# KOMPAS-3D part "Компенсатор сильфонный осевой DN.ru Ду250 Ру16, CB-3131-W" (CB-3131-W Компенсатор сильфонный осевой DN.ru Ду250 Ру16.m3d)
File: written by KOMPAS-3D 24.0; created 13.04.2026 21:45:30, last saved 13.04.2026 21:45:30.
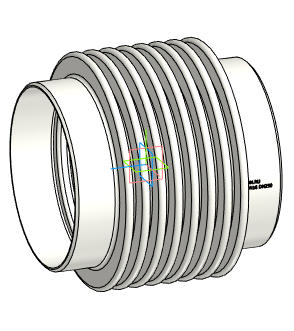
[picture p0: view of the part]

Document properties: Автор: DN.RU; Полное имя файла: D:\PROJECT CAD\DN.RU\...197(ACTUALE). CB-3131-W Компенсатор сильфонный осевой DN.ru\Исходники\DN250\CB-3131-W Компенсатор сильфонный осевой DN.ru Ду250 Ру16.m3d

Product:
- Body: Твердое тело1  | qty 1
    Масса: 21.471183
- Part/product: Компенсатор сильфонный осевой DN.ru Ду250 Ру16  | designation CB-3131-W
    Масса: 12.6
    Раздел спецификации: Прочие изделия
    Комментарий: D140-02128
    Примечание: D140-02128
    additional columns: Типовые

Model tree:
1. Твердое тело1  (labels: Твердое тело1)

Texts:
  CB-3131-W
